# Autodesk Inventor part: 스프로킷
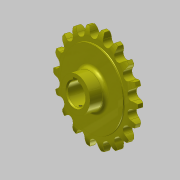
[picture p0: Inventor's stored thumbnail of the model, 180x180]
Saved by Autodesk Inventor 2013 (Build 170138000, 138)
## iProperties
Created: 2016-03
Part Number: 스프로킷
Material: 강철, 탄소
Document SubType Name: Modeling
Designer: mduedu
Density: 7.87 g/cm^3
Mass: 301.818 g
Surface Area: 124.882 cm^2
Volume: 38.3505 cm^3
Author: mduedu
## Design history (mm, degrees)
sketch "스케치1"
  geometry: L1 (0, 5)-(29.5, 5); L2 (29.5, 5)-(29.5, 4.1); L3 (30, 3.6)-(33.625, 3.6); L4 (40, 2)-(40, 0); L5 (40, 0)-(0, 0); L6 (0, 0)-(0, 5); L7 (0, -5)-(29.5, -5); L8 (29.5, -5)-(29.5, -4.1); L9 (30, -3.6)-(33.625, -3.6); L10 (40, -2)-(40, 0); L11 (0, 0)-(0, -5); A1 r 13.5 centre (33.625, -9.9) between (40, 2) and (33.625, 3.6); A2 r 13.5 centre (33.625, 9.9) between (33.625, -3.6) and (40, -2); A3 r 0.5 centre (30, 4.1) between (29.5, 4.1) and (30, 3.6); A4 r 0.5 centre (30, -4.1) between (30, -3.6) and (29.5, -4.1); 2 further points
  constraints: 22 end point, 8 point on circle, 6 symmetric about line, 5 tangent, 4 centre point, 4 parallel, 4 point on line, 1 equal radius, 1 horizontal, 1 perpendicular, 1 other
  dimensions: "d0" = 80 diameter of L4 L6; "d2" = 59 diameter of L2 L6; "d3" = 1.6 vertical distance of L4.start L3.end; "d4" = 3.6 distance from line of L4.end L3; "d5" = 5 distance between parallel lines of L5 L1; "d6" = 13.5 radius of A1; "d15" = 0.5 radius of A3
revolve "회전1" sketch "스케치1" stored, may be unused: angle "d7" = 90 deg
sketch "스케치2" dims "d8" = 65.2, "d11" = 80
  geometry: L1 (0, 0)-(0, 32.6); A1 r 36.57 centre (0, 0) between (-16.231, 32.771) and (0, 36.57); A2 r 3.97 centre (0, 36.57) between (-3.866, 35.665) and (0, 32.6); A3 r 12.7 centre (-16.231, 32.771) between (-3.866, 35.665) and (-5.534, 39.615); A4 r 12.7 centre (16.231, 32.771) between (5.534, 39.615) and (3.866, 35.665); A5 r 3.97 centre (0, 36.57) between (0, 32.6) and (3.866, 35.665); A6 r 40 centre (0, 0) between (5.534, 39.615) and (-5.534, 39.615); 2 further points
  constraints: 12 point on circle, 6 centre point, 4 coincident, 3 symmetric about line, 2 end point, 1 point on line, 1 tangent, 1 vertical, 1 vertical alignment, 7 other
  dimensions: "d10" = 73.14 diameter of A1; "d12" = 12.7 radius of A3
extrude "돌출1" cut sketch "스케치2" stored distance "d13" = 10; taper "d14" = 0 deg
sketch "스케치3"
  geometry: C1 r 13.5 at (0, 0); 1 further point
  constraints: 1 centre point, 1 coincident
  dimensions: "d19" = 27 diameter of C1
extrude "돌출2" join sketch "스케치3" distance "d20" = 13; taper "d21" = 0 deg
fillet "모깎기1" dims "d22" = 3
sketch "스케치4"
  geometry: L1 (-2.5, 0)-(2.5, 0); L2 (2.5, 0)-(2.5, 10.8); L3 (2.5, 10.8)-(-2.5, 10.8); L4 (-2.5, 10.8)-(-2.5, 0); C1 r 8.5 at (0, 0); 2 further points
  constraints: 8 end point, 2 coincident, 2 parallel, 1 centre point, 1 horizontal, 1 midpoint, 1 perpendicular
  dimensions: "d23" = 17 diameter of C1; "d25" = 5 distance of L2.end L3.end; "d26" = 10.8 distance of L1.end L2.end
extrude "돌출3" cut sketch "스케치4" stored distance "d27" = 8; taper "d28" = 0 deg
chamfer "모따기1" distance "d29" = 1; stored, may be unused: second distance "d30" = 2, angle "d31" = 45 deg
node "작업 평면1"
sketch "스케치5"
  geometry: L1 (13.5, 13)-(-13.5, 13) reference; 2 further points
  constraints: 1 vertical alignment
  dimensions: "d32" = 4 distance from line of point (0, 9) L1
hole "구멍1" sketch "스케치5" at (0, 9) diameter "d33" = 2.459; stored, may be unused: countersink angle "d37" = 90 deg, drill point angle "d39" = 118 deg; dims "d34" = 6, "d35" = 4, "d36" = 2, "d38" = 8
node "솔리드1"
pattern_circular "원형 패턴1" dims angle "d17" = 360 deg
